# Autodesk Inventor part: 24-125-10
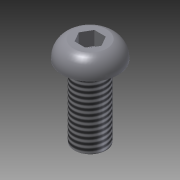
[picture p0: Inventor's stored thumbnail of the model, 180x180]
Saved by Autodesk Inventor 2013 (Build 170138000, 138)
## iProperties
Created: 2004-10
Part Number: 24-125-10
Material: Stahl (hohe Festigk., niedr. Legier.)
Document SubType Name: Modeling
Designer: Autodesk, Inc.
Manufacturer: Standard
Standards Organization: Custom
Description: SCREW, PARKER IPS, BUTTON HEAD, M10X25
Catalog Web Link: http://www.parker.com/ead/cm1.asp?cmid=809
Vendor: PARKER IPS
Mass: 10.8823 g
Surface Area: 9.37524 cm^2
Volume: 1.38805 cm^3
Density: 7.84 g/cm^3
CAGE: 1LJX3
Dept. ID: Product Design
Description #2: ---
Finish #1: ---
Finish #2: ---
Material ID: ---
Project Number: ---
Author: Autodesk, Inc.
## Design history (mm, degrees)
derived "2X-YYY-ZZ IPS Screws.ipt"
body "Solid1"
tag "TaggingFeature2"
feature "Solid1::2X-YYY-ZZ IPS Screws.ipt" dims "ScaleForDerivedMember" = 10
